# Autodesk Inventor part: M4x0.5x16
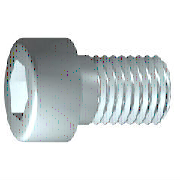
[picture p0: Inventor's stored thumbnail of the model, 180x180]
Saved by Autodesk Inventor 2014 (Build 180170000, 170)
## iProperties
Created: 2009-02
Part Number: M4x0.5x16
Material: 강, 연강
Description: 6각머리 태핑 나사
Document SubType Name: Modeling
Standard: KS B 1003
Designer: 한국산업디자인학원
Standards Organization: KS
Language: ko-KR
Size Designation: M 4 x 16
Categories: <MemberInstance><Categories><Category DisplayName="조임쇠" InternalName="e4da775c-781d-43d5-af7c-5136215cf5a6" Mnemonic="FSTN"><Category DisplayName="볼트" InternalN
Density: 1 g/cm^3
Appearance: 강철
IsCustomPart: 1
Author: 한국산업디자인학원
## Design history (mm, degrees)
sketch "스케치1"
  geometry: L1 (-1, 0)-(16, 0); L2 (16, 0)-(16, 2); L3 (16, 2)-(1.75, 2); L4 (1.75, 2)-(1.32, 2); L5 (1.32, 2)-(0, 2); L6 (0, 2)-(0, 3.5); L7 (0, 3.5)-(-4, 3.5); L8 (-4, 3.5)-(-4, 1.732); L9 (-4, 1.732)-(-2, 1.732); L10 (-2, 1.732)-(-1, 0); L11 (-8, 0)-(20, 0) reference; L12 (0, -0.7)-(0, 4.2) reference; L13 (1.75, 2)-(0, 2)
  constraints: 22 end point, 6 parallel, 2 collinear, 2 perpendicular, 1 horizontal, 1 point on line
  dimensions: "d1" = 14.25 distance from line of L3.end L2 (= GEL); "d2" = 0.42952 distance of L4.end L3.end (computed from GAL); "d3" = 4 distance between parallel lines of L8 L6 (= KOH); "d4" = 2 distance of L8.end L9.end (= INTI); "d5" = 60 deg angle of L10 L1; "d6" = 4 diameter of L3 L1 (= GD); "d7" = 4 diameter of L5 L1 (= BDM); "d8" = 3.4641 diameter of L9 L1 (= 1.1547 x SW); "d9" = 7 diameter of L7 L1 (= KOD); "d26" = 16 distance between parallel lines of L12 L2 (= NLG)
revolve "본체" sketch "스케치1" stored, may be unused: angle "d10" = 90 deg
sketch "스케치2"
  geometry: L1 (0, -4.9)-(0, 4.9) reference; L2 (-4.9, 0)-(4.9, 0) reference; L3 (1.732, 0)-(0.866, -1.5); L4 (0.866, -1.5)-(-0.866, -1.5); L5 (-0.866, -1.5)-(-1.732, 0); L6 (-1.732, 0)-(-0.866, 1.5); L7 (-0.866, 1.5)-(0.866, 1.5); L8 (0.866, 1.5)-(1.732, 0); 2 further points
  constraints: 12 end point, 1 coincident, 1 horizontal alignment, 1 point on line, 12 other
extrude "슬롯" join sketch "스케치2" stored distance "d11" = 10; taper "d12" = 0 deg
workplane "Work Plane1"
fillet "Fillet2" dims "d30" = 0.1 (= R)
body "Solid1"
fillet "모깎기1" dims "d17" = 0.4 (= RR)
feature "스레드" dims "d13" = 14.25 (= GEL), "d14" = 0
chamfer "모따기1" distance "d15" = 0.42941 (= -0.5 x SPD + 0.5 x GD); stored, may be unused: second distance "d16" = 0.42941 (= GUL), angle "d27" = 45 deg
other parameters: "GD" = 4 (= NND) [user parameter; used in 2 equation terms], "NLG" = 16 [user parameter; used in 1 equation term], "GEL" = 14.25 [user parameter; used in 2 equation terms], "KOD" = 7 [user parameter; used in 1 equation term], "KOH" = 4 [user parameter; used in 1 equation term], "INTI" = 2 [user parameter; used in 1 equation term], "GAL" = 0.42941 (= 0.61345 x PTC) [user parameter; used in 1 equation term], "GUL" = 0.42941 (= 0.61345 x PTC) [user parameter; used in 1 equation term], "BDM" = 4 (= NND) [user parameter; used in 1 equation term], "SW" = 3 [user parameter; used in 2 equation terms], "RR" = 0.4 [user parameter; used in 1 equation term], "SPD" = 3.14117 (= NND - 1.2269 x PTC) [user parameter; used in 1 equation term], "d19" = 0, "d28" = 0, "d29" = 0, "R" = 0.1 [user parameter; used in 1 equation term], "PHH" = 0.2 [user parameter], "GD1" = 3.14117 (= THREADDIA - 1.2269 x PTC) [user parameter], "THREADDIA" = 4 [user parameter; used in 1 equation term], "FAWI" = 45 deg [user parameter], "TPU" = 14.28571 (computed from PTC) [user parameter], "PTC" = 0.7 [user parameter; used in 5 equation terms], "NND" = 4 [user parameter; used in 3 equation terms], "TOA" = 30 deg [user parameter], "E0" = 3.465 (= 1.155 x SW) [user parameter]
